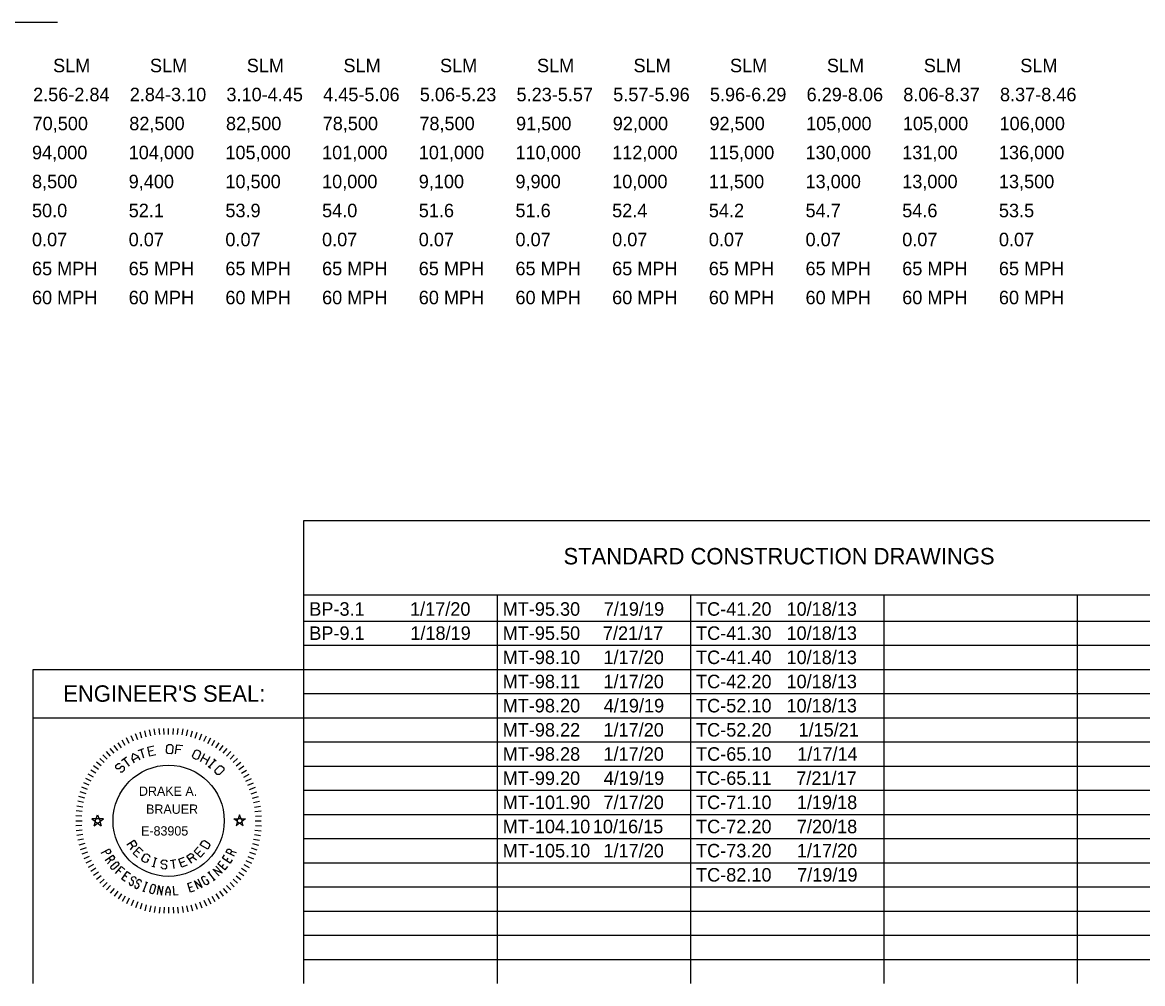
# Model space of a CAD drawing. Extents: x -17.5 to 72.9, y -57.8 to 32.3.
# Drawn here: x 8.08 to 19.67, y -47.95 to -38 of the extents above; entities that cross this region are included whole.
import ezdxf

# ---------------------------------------------------------------- set-up
doc = ezdxf.new("R2010")
doc.units = 0
doc.layers.add('Default', color=7, linetype='Continuous')
doc.layers.add('SH_Data', color=7, linetype='Continuous')

msp = doc.modelspace()

# ---------------------------------------------------------------- linework, layer by layer
at = {"layer": 'Default'}
for p, q in [((9.188, -45.46), (9.16, -45.404)), ((9.231, -45.439), (9.206, -45.382)), ((9.275, -45.422), (9.252, -45.363)), ((9.319, -45.406), (9.3, -45.346)), ((9.364, -45.393), (9.348, -45.332)), ((9.41, -45.382), (9.397, -45.321)), ((9.456, -45.373), (9.447, -45.311)), ((9.503, -45.367), (9.496, -45.305)), ((9.548, -45.369), (9.545, -45.306)), ((9.595, -45.367), (9.595, -45.305)), ((9.595, -45.367), (9.595, -45.305)), ((9.642, -45.369), (9.645, -45.306)), ((9.688, -45.367), (9.694, -45.305)), ((9.734, -45.373), (9.744, -45.311)), ((9.78, -45.382), (9.793, -45.321)), ((9.826, -45.393), (9.842, -45.332)), ((9.871, -45.406), (9.89, -45.346)), ((9.916, -45.422), (9.938, -45.363)), ((9.959, -45.439), (9.985, -45.382)), ((10.002, -45.46), (10.03, -45.404)), ((9.031, -45.562), (8.991, -45.513)), ((9.068, -45.533), (9.031, -45.482)), ((9.107, -45.507), (9.073, -45.454)), ((9.147, -45.482), (9.116, -45.428)), ((10.043, -45.482), (10.074, -45.428)), ((10.083, -45.507), (10.117, -45.454)), ((10.122, -45.533), (10.159, -45.482)), ((10.159, -45.562), (10.199, -45.513)), ((8.928, -45.658), (8.882, -45.616)), ((8.961, -45.625), (8.916, -45.58)), ((8.995, -45.592), (8.953, -45.545)), ((10.195, -45.592), (10.237, -45.545)), ((10.23, -45.625), (10.274, -45.58)), ((10.262, -45.658), (10.308, -45.616)), ((8.842, -45.77), (8.79, -45.736)), ((8.869, -45.732), (8.818, -45.694)), ((8.897, -45.694), (8.849, -45.655)), ((10.292, -45.694), (10.341, -45.655)), ((10.321, -45.732), (10.372, -45.694)), ((10.348, -45.77), (10.4, -45.736)), ((8.774, -45.894), (8.717, -45.868)), ((8.795, -45.852), (8.739, -45.823)), ((8.818, -45.81), (8.763, -45.779)), ((10.373, -45.81), (10.427, -45.779)), ((10.395, -45.852), (10.451, -45.823)), ((10.415, -45.894), (10.473, -45.868)), ((8.741, -45.982), (8.681, -45.963)), ((8.757, -45.938), (8.698, -45.915)), ((10.433, -45.938), (10.492, -45.915)), ((10.449, -45.982), (10.509, -45.963)), ((8.708, -46.119), (8.645, -46.109)), ((8.716, -46.073), (8.655, -46.059)), ((8.727, -46.027), (8.667, -46.011)), ((10.463, -46.027), (10.523, -46.011)), ((10.474, -46.073), (10.536, -46.059)), ((10.482, -46.119), (10.545, -46.109)), ((8.698, -46.213), (8.635, -46.209)), ((8.701, -46.166), (8.639, -46.159)), ((8.846, -46.242), (8.861, -46.198)), ((8.861, -46.198), (8.875, -46.242)), ((10.329, -46.198), (10.315, -46.242)), ((10.344, -46.242), (10.329, -46.198)), ((10.488, -46.166), (10.552, -46.159)), ((10.492, -46.213), (10.555, -46.209)), ((8.698, -46.31), (8.635, -46.314)), ((8.637, -46.261), (8.701, -46.261)), ((8.846, -46.242), (8.801, -46.242)), ((8.801, -46.242), (8.838, -46.269)), ((8.824, -46.313), (8.838, -46.269)), ((8.824, -46.313), (8.861, -46.285)), ((8.861, -46.285), (8.897, -46.313)), ((8.921, -46.242), (8.875, -46.242)), ((8.884, -46.269), (8.921, -46.242)), ((8.884, -46.269), (8.897, -46.313)), ((10.269, -46.242), (10.315, -46.242)), ((10.306, -46.269), (10.269, -46.242)), ((10.306, -46.269), (10.293, -46.313)), ((10.329, -46.285), (10.293, -46.313)), ((10.367, -46.313), (10.329, -46.285)), ((10.344, -46.242), (10.389, -46.242)), ((10.389, -46.242), (10.352, -46.269)), ((10.367, -46.313), (10.352, -46.269)), ((10.489, -46.261), (10.553, -46.261)), ((10.492, -46.31), (10.555, -46.314)), ((8.701, -46.357), (8.639, -46.364)), ((8.708, -46.404), (8.645, -46.414)), ((8.716, -46.45), (8.655, -46.463)), ((10.474, -46.45), (10.536, -46.463)), ((10.482, -46.404), (10.545, -46.414)), ((10.488, -46.357), (10.552, -46.364)), ((8.727, -46.496), (8.667, -46.512)), ((8.741, -46.541), (8.681, -46.56)), ((10.449, -46.541), (10.509, -46.56)), ((10.463, -46.496), (10.523, -46.512)), ((8.757, -46.585), (8.698, -46.608)), ((8.774, -46.629), (8.717, -46.654)), ((8.795, -46.671), (8.739, -46.7)), ((10.395, -46.671), (10.451, -46.7)), ((10.415, -46.629), (10.473, -46.654)), ((10.433, -46.585), (10.492, -46.608)), ((8.818, -46.713), (8.763, -46.744)), ((8.842, -46.752), (8.79, -46.787)), ((8.869, -46.791), (8.818, -46.828)), ((10.321, -46.791), (10.372, -46.828)), ((10.348, -46.752), (10.4, -46.787)), ((10.373, -46.713), (10.427, -46.744)), ((8.897, -46.829), (8.849, -46.868)), ((8.928, -46.864), (8.882, -46.906)), ((8.961, -46.898), (8.916, -46.943)), ((10.23, -46.898), (10.274, -46.943)), ((10.262, -46.864), (10.308, -46.906)), ((10.292, -46.829), (10.341, -46.868)), ((8.995, -46.93), (8.953, -46.977)), ((9.031, -46.961), (8.991, -47.01)), ((9.068, -46.99), (9.031, -47.04)), ((9.107, -47.017), (9.073, -47.069)), ((10.083, -47.017), (10.117, -47.069)), ((10.122, -46.99), (10.159, -47.04)), ((10.159, -46.961), (10.199, -47.01)), ((10.195, -46.93), (10.237, -46.977)), ((9.147, -47.041), (9.116, -47.095)), ((9.188, -47.063), (9.16, -47.119)), ((9.231, -47.083), (9.206, -47.141)), ((9.275, -47.101), (9.252, -47.16)), ((9.319, -47.117), (9.3, -47.176)), ((9.364, -47.13), (9.348, -47.191)), ((9.41, -47.141), (9.397, -47.203)), ((9.456, -47.149), (9.447, -47.211)), ((9.734, -47.149), (9.744, -47.211)), ((9.78, -47.141), (9.793, -47.203)), ((9.826, -47.13), (9.842, -47.191)), ((9.871, -47.117), (9.89, -47.176)), ((9.916, -47.101), (9.938, -47.16)), ((9.959, -47.083), (9.985, -47.141)), ((10.002, -47.063), (10.03, -47.119)), ((10.043, -47.041), (10.074, -47.095)), ((9.503, -47.156), (9.496, -47.218)), ((9.548, -47.154), (9.545, -47.217)), ((9.595, -47.156), (9.595, -47.218)), ((9.595, -47.156), (9.595, -47.218)), ((9.642, -47.154), (9.645, -47.217)), ((9.688, -47.156), (9.694, -47.218))]:
    msp.add_line(p, q, dxfattribs=at)
for points in [[(9.279, -45.534), (9.34, -45.514)], [(9.34, -45.614), (9.31, -45.524)], [(9.463, -45.578), (9.4, -45.593), (9.379, -45.501), (9.441, -45.486)], [(9.572, -45.548), (9.575, -45.485), (9.592, -45.471), (9.623, -45.471), (9.639, -45.488), (9.636, -45.551), (9.62, -45.567), (9.588, -45.565), (9.572, -45.548)], [(9.667, -45.57), (9.68, -45.476), (9.743, -45.484)], [(9.721, -45.528), (9.673, -45.522)], [(9.842, -45.592), (9.868, -45.535), (9.889, -45.528), (9.918, -45.54), (9.926, -45.561), (9.901, -45.619), (9.88, -45.627), (9.851, -45.615), (9.842, -45.592)], [(9.108, -45.637), (9.161, -45.601)], [(9.189, -45.697), (9.135, -45.619)], [(9.242, -45.662), (9.218, -45.62), (9.224, -45.564), (9.274, -45.589), (9.298, -45.631)], [(9.282, -45.603), (9.226, -45.634)], [(9.436, -45.535), (9.389, -45.546)], [(9.923, -45.648), (9.969, -45.565)], [(10.002, -45.637), (9.946, -45.606)], [(9.979, -45.679), (10.025, -45.596)], [(10.016, -45.707), (10.076, -45.634)], [(10.088, -45.644), (10.064, -45.624)], [(9.094, -45.756), (9.117, -45.756), (9.139, -45.734), (9.139, -45.711), (9.127, -45.7), (9.105, -45.7), (9.083, -45.722), (9.06, -45.723), (9.049, -45.713), (9.05, -45.689), (9.072, -45.667), (9.094, -45.667)], [(10.003, -45.697), (10.028, -45.717)], [(10.076, -45.736), (10.12, -45.691), (10.143, -45.692), (10.166, -45.714), (10.166, -45.737), (10.121, -45.781), (10.098, -45.781), (10.076, -45.759), (10.076, -45.736)], [(8.898, -46.595), (8.982, -46.55), (8.997, -46.578), (8.988, -46.595), (8.974, -46.602), (8.956, -46.6), (8.941, -46.572)], [(9.164, -46.511), (9.237, -46.461), (9.262, -46.498), (9.258, -46.519), (9.246, -46.528), (9.226, -46.523), (9.201, -46.486)], [(9.226, -46.523), (9.197, -46.561)], [(9.272, -46.64), (9.229, -46.599), (9.289, -46.535), (9.333, -46.575)], [(9.293, -46.597), (9.259, -46.566)], [(9.966, -46.593), (9.924, -46.637), (9.86, -46.575), (9.901, -46.532)], [(9.999, -46.556), (9.922, -46.51), (9.946, -46.472), (9.966, -46.466), (10.016, -46.497), (10.022, -46.517), (9.999, -46.556)], [(10.276, -46.627), (10.19, -46.585), (10.204, -46.556), (10.223, -46.553), (10.237, -46.56), (10.246, -46.576), (10.232, -46.605)], [(8.939, -46.671), (9.017, -46.616), (9.036, -46.642), (9.029, -46.66), (9.016, -46.669), (8.997, -46.669), (8.979, -46.643)], [(8.997, -46.669), (8.964, -46.705)], [(9.001, -46.73), (9.048, -46.689), (9.067, -46.686), (9.081, -46.702), (9.077, -46.72), (9.03, -46.762), (9.01, -46.765), (8.996, -46.75), (9.001, -46.73)], [(9.373, -46.656), (9.386, -46.663), (9.371, -46.689), (9.351, -46.694), (9.325, -46.679), (9.319, -46.658), (9.349, -46.608), (9.37, -46.603), (9.395, -46.618), (9.401, -46.638)], [(9.437, -46.733), (9.464, -46.648)], [(9.478, -46.653), (9.449, -46.644)], [(9.515, -46.738), (9.53, -46.755), (9.559, -46.757), (9.575, -46.743), (9.576, -46.728), (9.563, -46.713), (9.533, -46.71), (9.519, -46.695), (9.52, -46.68), (9.537, -46.666), (9.566, -46.669), (9.58, -46.685)], [(9.612, -46.672), (9.671, -46.663)], [(9.654, -46.755), (9.642, -46.667)], [(9.788, -46.72), (9.732, -46.741), (9.701, -46.658), (9.757, -46.637)], [(9.758, -46.683), (9.716, -46.699)], [(9.834, -46.7), (9.785, -46.626), (9.822, -46.601), (9.843, -46.605), (9.851, -46.617), (9.847, -46.637), (9.809, -46.662)], [(9.847, -46.637), (9.884, -46.666)], [(9.923, -46.573), (9.891, -46.605)], [(10.205, -46.735), (10.178, -46.768), (10.104, -46.708), (10.131, -46.675)], [(10.253, -46.664), (10.231, -46.7), (10.151, -46.649), (10.173, -46.613)], [(10.208, -46.647), (10.19, -46.674)], [(10.246, -46.576), (10.294, -46.588)], [(9.046, -46.806), (9.109, -46.735), (9.141, -46.764)], [(9.102, -46.791), (9.078, -46.77)], [(9.145, -46.888), (9.11, -46.864), (9.165, -46.786), (9.2, -46.811)], [(9.423, -46.729), (9.451, -46.737)], [(10.018, -46.789), (10.002, -46.802)], [(10.068, -46.871), (10.01, -46.796)], [(10.118, -46.83), (10.051, -46.762), (10.148, -46.8), (10.082, -46.732)], [(10.161, -46.713), (10.141, -46.738)], [(9.164, -46.843), (9.138, -46.824)], [(9.188, -46.9), (9.19, -46.919), (9.208, -46.929), (9.225, -46.92), (9.233, -46.906), (9.232, -46.887), (9.213, -46.877), (9.211, -46.859), (9.218, -46.845), (9.235, -46.836), (9.253, -46.846), (9.256, -46.865)], [(9.244, -46.93), (9.246, -46.95), (9.264, -46.96), (9.281, -46.95), (9.289, -46.936), (9.287, -46.917), (9.269, -46.907), (9.266, -46.889), (9.274, -46.875), (9.291, -46.866), (9.309, -46.876), (9.311, -46.895)], [(9.334, -46.988), (9.37, -46.9)], [(9.38, -46.904), (9.36, -46.896)], [(9.4, -46.991), (9.417, -46.93), (9.432, -46.918), (9.452, -46.924), (9.458, -46.942), (9.442, -47.002), (9.427, -47.016), (9.407, -47.01), (9.4, -46.991)], [(9.862, -46.987), (9.821, -46.999), (9.792, -46.909), (9.833, -46.896)], [(9.902, -46.97), (9.862, -46.883), (9.941, -46.952), (9.901, -46.865)], [(9.982, -46.873), (9.99, -46.868), (10.007, -46.895), (10.007, -46.915), (9.989, -46.925), (9.97, -46.917), (9.938, -46.863), (9.939, -46.844), (9.957, -46.833), (9.974, -46.841)], [(10.06, -46.878), (10.077, -46.865)], [(9.324, -46.984), (9.344, -46.992)], [(9.48, -47.025), (9.494, -46.93), (9.522, -47.031), (9.537, -46.937)], [(9.566, -47.032), (9.568, -46.984), (9.591, -46.938), (9.61, -46.986), (9.609, -47.034)], [(9.61, -47.002), (9.567, -47)], [(9.695, -47.027), (9.652, -47.031), (9.644, -46.936)], [(9.837, -46.944), (9.806, -46.954)]]:
    msp.add_lwpolyline(points, dxfattribs=at)
for centre, radius in [((9.595, -46.261), 0.575), ((8.861, -46.261), 0.0239), ((10.33, -46.261), 0.0239)]:
    msp.add_circle(centre, radius, dxfattribs=at)
at = {"layer": 'SH_Data'}
for p, q in [((8.445, -38.002), (7.195, -38.002)), ((10.995, -43.154), (24.445, -43.154)), ((10.995, -47.945), (10.995, -43.154)), ((10.995, -43.924), (24.445, -43.924)), ((12.995, -47.945), (12.995, -43.924)), ((14.995, -47.945), (14.995, -43.924)), ((16.995, -47.945), (16.995, -43.924)), ((18.995, -47.945), (18.995, -43.924)), ((10.995, -44.195), (24.445, -44.195)), ((10.995, -44.445), (24.445, -44.445)), ((8.195, -47.945), (8.195, -44.695)), ((8.195, -44.695), (10.995, -44.695)), ((10.995, -44.695), (24.445, -44.695)), ((10.995, -44.945), (24.445, -44.945)), ((8.195, -45.195), (10.995, -45.195)), ((10.995, -45.195), (24.445, -45.195)), ((10.995, -45.445), (24.445, -45.445)), ((10.995, -45.695), (24.445, -45.695)), ((10.995, -45.945), (24.445, -45.945)), ((10.995, -46.195), (24.445, -46.195)), ((10.995, -46.445), (24.445, -46.445)), ((10.995, -46.695), (24.445, -46.695)), ((10.995, -46.945), (24.445, -46.945)), ((10.995, -47.195), (24.445, -47.195)), ((10.995, -47.445), (24.445, -47.445)), ((10.995, -47.695), (24.445, -47.695))]:
    msp.add_line(p, q, dxfattribs=at)

# ---------------------------------------------------------------- texts
at = {"layer": 'Default'}
for s, height, p in [("ENGINEER'S SEAL:", 0.17, (8.505, -45.03)), ('DRAKE A.', 0.0965, (9.288, -46.003)), ('BRAUER', 0.0965, (9.362, -46.189)), ('E-83905', 0.0965, (9.31, -46.414))]:
    msp.add_text(s, height=height, dxfattribs=at).set_placement(p)
at = {"layer": 'SH_Data'}
for s, height, p in [('SLM', 0.14, (8.4, -38.518)), ('SLM', 0.14, (9.402, -38.518)), ('SLM', 0.14, (10.403, -38.518)), ('SLM', 0.14, (11.403, -38.518)), ('SLM', 0.14, (12.402, -38.518)), ('SLM', 0.14, (13.405, -38.518)), ('SLM', 0.14, (14.403, -38.518)), ('SLM', 0.14, (15.401, -38.518)), ('SLM', 0.14, (16.403, -38.518)), ('SLM', 0.14, (17.405, -38.518)), ('SLM', 0.14, (18.403, -38.518)), ('2.56-2.84', 0.14, (8.193, -38.818)), ('2.84-3.10', 0.14, (9.193, -38.818)), ('3.10-4.45', 0.14, (10.193, -38.818)), ('4.45-5.06', 0.14, (11.193, -38.818)), ('5.06-5.23', 0.14, (12.193, -38.818)), ('5.23-5.57', 0.14, (13.193, -38.818)), ('5.57-5.96', 0.14, (14.193, -38.818)), ('5.96-6.29', 0.14, (15.193, -38.818)), ('6.29-8.06', 0.14, (16.193, -38.818)), ('8.06-8.37', 0.14, (17.193, -38.818)), ('8.37-8.46', 0.14, (18.193, -38.818)), ('70,500', 0.14, (8.188, -39.118)), ('82,500', 0.14, (9.188, -39.118)), ('82,500', 0.14, (10.188, -39.118)), ('78,500', 0.14, (11.188, -39.118)), ('78,500', 0.14, (12.188, -39.118)), ('91,500', 0.14, (13.188, -39.118)), ('92,000', 0.14, (14.188, -39.118)), ('92,500', 0.14, (15.188, -39.118)), ('105,000', 0.14, (16.188, -39.118)), ('105,000', 0.14, (17.188, -39.118)), ('106,000', 0.14, (18.188, -39.118)), ('94,000', 0.14, (8.182, -39.418)), ('104,000', 0.14, (9.182, -39.418)), ('105,000', 0.14, (10.182, -39.418)), ('101,000', 0.14, (11.182, -39.418)), ('101,000', 0.14, (12.182, -39.418)), ('110,000', 0.14, (13.182, -39.418)), ('112,000', 0.14, (14.182, -39.418)), ('115,000', 0.14, (15.182, -39.418)), ('130,000', 0.14, (16.182, -39.418)), ('131,00', 0.14, (17.182, -39.418)), ('136,000', 0.14, (18.182, -39.418)), ('8,500', 0.14, (8.182, -39.718)), ('9,400', 0.14, (9.182, -39.718)), ('10,500', 0.14, (10.182, -39.718)), ('10,000', 0.14, (11.182, -39.718)), ('9,100', 0.14, (12.182, -39.718)), ('9,900', 0.14, (13.182, -39.718)), ('10,000', 0.14, (14.182, -39.718)), ('11,500', 0.14, (15.182, -39.718)), ('13,000', 0.14, (16.182, -39.718)), ('13,000', 0.14, (17.182, -39.718)), ('13,500', 0.14, (18.182, -39.718)), ('50.0', 0.14, (8.182, -40.018)), ('52.1', 0.14, (9.182, -40.018)), ('53.9', 0.14, (10.182, -40.018)), ('54.0', 0.14, (11.182, -40.018)), ('51.6', 0.14, (12.182, -40.018)), ('51.6', 0.14, (13.182, -40.018)), ('52.4', 0.14, (14.182, -40.018)), ('54.2', 0.14, (15.182, -40.018)), ('54.7', 0.14, (16.182, -40.018)), ('54.6', 0.14, (17.182, -40.018)), ('53.5', 0.14, (18.182, -40.018)), ('0.07', 0.14, (8.182, -40.318)), ('0.07', 0.14, (9.182, -40.318)), ('0.07', 0.14, (10.182, -40.318)), ('0.07', 0.14, (11.182, -40.318)), ('0.07', 0.14, (12.182, -40.318)), ('0.07', 0.14, (13.182, -40.318)), ('0.07', 0.14, (14.182, -40.318)), ('0.07', 0.14, (15.182, -40.318)), ('0.07', 0.14, (16.182, -40.318)), ('0.07', 0.14, (17.182, -40.318)), ('0.07', 0.14, (18.182, -40.318)), ('65 MPH', 0.14, (8.182, -40.618)), ('65 MPH', 0.14, (9.182, -40.618)), ('65 MPH', 0.14, (10.182, -40.618)), ('65 MPH', 0.14, (11.182, -40.618)), ('65 MPH', 0.14, (12.182, -40.618)), ('65 MPH', 0.14, (13.182, -40.618)), ('65 MPH', 0.14, (14.182, -40.618)), ('65 MPH', 0.14, (15.182, -40.618)), ('65 MPH', 0.14, (16.182, -40.618)), ('65 MPH', 0.14, (17.182, -40.618)), ('65 MPH', 0.14, (18.182, -40.618)), ('60 MPH', 0.14, (8.182, -40.918)), ('60 MPH', 0.14, (9.182, -40.918)), ('60 MPH', 0.14, (10.182, -40.918)), ('60 MPH', 0.14, (11.182, -40.918)), ('60 MPH', 0.14, (12.182, -40.918)), ('60 MPH', 0.14, (13.182, -40.918)), ('60 MPH', 0.14, (14.182, -40.918)), ('60 MPH', 0.14, (15.182, -40.918)), ('60 MPH', 0.14, (16.182, -40.918)), ('60 MPH', 0.14, (17.182, -40.918)), ('60 MPH', 0.14, (18.182, -40.918)), ('STANDARD CONSTRUCTION DRAWINGS', 0.17, (13.679, -43.609)), ('BP-3.1', 0.14, (11.05, -44.14)), ('1/17/20', 0.14, (12.092, -44.14)), ('MT-95.30', 0.14, (13.05, -44.14)), ('7/19/19', 0.14, (14.095, -44.14)), ('TC-41.20', 0.14, (15.05, -44.14)), ('10/18/13', 0.14, (15.985, -44.14)), ('BP-9.1', 0.14, (11.05, -44.39)), ('1/18/19', 0.14, (12.095, -44.39)), ('MT-95.50', 0.14, (13.05, -44.39)), ('7/21/17', 0.14, (14.086, -44.39)), ('TC-41.30', 0.14, (15.05, -44.39)), ('10/18/13', 0.14, (15.985, -44.39)), ('MT-98.10', 0.14, (13.05, -44.64)), ('1/17/20', 0.14, (14.092, -44.64)), ('TC-41.40', 0.14, (15.05, -44.64)), ('10/18/13', 0.14, (15.985, -44.64)), ('MT-98.11', 0.14, (13.05, -44.89)), ('1/17/20', 0.14, (14.092, -44.89)), ('TC-42.20', 0.14, (15.05, -44.89)), ('10/18/13', 0.14, (15.985, -44.89)), ('MT-98.20', 0.14, (13.05, -45.14)), ('4/19/19', 0.14, (14.095, -45.14)), ('TC-52.10', 0.14, (15.05, -45.14)), ('10/18/13', 0.14, (15.985, -45.14)), ('MT-98.22', 0.14, (13.05, -45.39)), ('1/17/20', 0.14, (14.092, -45.39)), ('TC-52.20', 0.14, (15.05, -45.39)), ('1/15/21', 0.14, (16.109, -45.39)), ('MT-98.28', 0.14, (13.05, -45.64)), ('1/17/20', 0.14, (14.092, -45.64)), ('TC-65.10', 0.14, (15.05, -45.64)), ('1/17/14', 0.14, (16.096, -45.64)), ('MT-99.20', 0.14, (13.05, -45.89)), ('4/19/19', 0.14, (14.095, -45.89)), ('TC-65.11', 0.14, (15.05, -45.89)), ('7/21/17', 0.14, (16.086, -45.89)), ('7/17/20', 0.14, (14.092, -46.14)), ('1/19/18', 0.14, (16.092, -46.14)), ('MT-101.90', 0.14, (13.05, -46.14)), ('TC-71.10', 0.14, (15.05, -46.14)), ('MT-104.10', 0.14, (13.05, -46.39)), ('10/16/15', 0.14, (13.982, -46.39)), ('TC-72.20', 0.14, (15.05, -46.39)), ('7/20/18', 0.14, (16.092, -46.39)), ('MT-105.10', 0.14, (13.05, -46.64)), ('1/17/20', 0.14, (14.092, -46.64)), ('TC-73.20', 0.14, (15.05, -46.64)), ('1/17/20', 0.14, (16.092, -46.64)), ('TC-82.10', 0.14, (15.05, -46.89)), ('7/19/19', 0.14, (16.095, -46.89))]:
    msp.add_text(s, height=height, dxfattribs=at).set_placement(p)

doc.saveas('drawing.dxf')
